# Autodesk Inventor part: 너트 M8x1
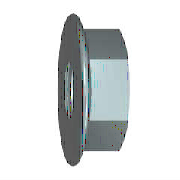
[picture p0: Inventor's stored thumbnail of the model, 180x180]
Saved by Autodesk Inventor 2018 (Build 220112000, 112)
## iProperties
Created: 2015-12
Part Number: 너트 M8x1
Material: 스테인리스강
Description: 플랜지붙이 6각 너트 - 일반 스레드
Document SubType Name: Modeling
Standard: ISO 4161
Designer: mdu
Standard Revision: 2판 1999-03-15
Standards Organization: ISO
Language: ko-KR
Size Designation: M8
Categories: <MemberInstance><Categories><Category DisplayName="조임쇠" InternalName="e4da775c-781d-43d5-af7c-5136215cf5a6" Mnemonic="FSTN"><Category DisplayName="너트" InternalN
Density: 8.08 g/cm^3
Mass: 8.84458 g
Surface Area: 8.9064 cm^2
Volume: 1.09463 cm^3
Appearance: 강철
Author: mdu
IsCustomPart: 1
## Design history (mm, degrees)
sketch "스케치1"
  geometry: L1 (-1.844, 0)-(9.641, 0) reference; L2 (3.107, 6.5)-(2.288, 8.257); L3 (3.107, 6.5)-(8, 6.5); L4 (8, 6.5)-(8, 0); L5 (3.107, 6.5)-(3.107, 0); L6 (0, -1.835)-(0, 11.01) reference; A1 r 1.2 centre (1.2, 7.75) between (2.288, 8.257) and (0, 7.75); 1 further point
  constraints: 8 end point, 3 point on line, 2 perpendicular, 2 point on circle, 2 tangent, 1 centre point, 1 parallel
  dimensions: "d2" = 13 diameter of L3 L1 (= SW); "d4" = 17.9 dimension on A1 L1 (= LADI); "d5" = 1.2 radius of A1 (= PHH); "d15" = 8 distance between parallel lines of L4 L6 (= KOH); "d16" = 25 deg angle of L6 L2 (= KEWI)
revolve "링" sketch "스케치1" stored, may be unused: angle "d8" = 90 deg
sketch "스케치2"
  geometry: L1 (-6.5, -3.753)-(-6.5, 3.753); L2 (-6.5, 3.753)-(0, 7.506); L3 (0, 7.506)-(6.5, 3.753); L4 (6.5, 3.753)-(6.5, -3.753); L5 (6.5, -3.753)-(0, -7.506); L6 (0, -7.506)-(-6.5, -3.753); C1 r 4.9 at (0, 0); C2 r 7.75 at (0, 0) reference; 1 further point
  constraints: 12 end point, 1 centre point, 1 coincident, 1 vertical, 11 other
  dimensions: "d6" = 15.01111 distance of L5.end L2.end (= 1.1547 x SW)
extrude "본체" join sketch "스케치2" distance "d7" = 8 (= KOH); taper "d9" = 0 deg
sketch "스케치3"
  geometry: L1 (2.638, 7.506)-(8, 7.506) reference; L2 (8, 3.753)-(8, 7.506) reference; L3 (0, -7.75)-(0, 7.75) reference; L4 (-1.6, 0)-(9.6, 0) reference; L5 (7.419, 7.506)-(8, 6.5)
  constraints: 2 end point, 2 point on line
  dimensions: "d10" = 30 deg angle of L2 L5 (= ANG1); "d11" = 13 diameter of L5.end L4 (= SW0)
revolve "모따기1" sketch "스케치3" stored, may be unused: angle "d24" = 90 deg
sketch "스케치4"
  geometry: C1 r 7.75 at (0, 0) reference; 1 further point
  constraints: 1 coincident
hole "스레드" sketch "스케치4" at (0, 0) diameter "d25" = 6.917; stored, may be unused: countersink angle "d29" = 82 deg, drill point angle "d31" = 118 deg; dims "d26" = 6, "d27" = 4, "d28" = 2, "d30" = 8
workaxis "Work Axis1"
workplane "Work Plane1"
body "Solid1"
chamfer "모따기2" distance "d12" = 0.67658 (= -0.5 x GD1 + 0.5 x NND); stored, may be unused: angle "d13" = 30 deg, second distance "d46" = 0.67658 (= -0.5 x GD1 + 0.5 x NND)
chamfer "모따기3" distance "d51" = 0.67658 (= -0.5 x GD1 + 0.5 x NND); stored, may be unused: second distance "d52" = 2, angle "d53" = 45 deg
other parameters: "ANG1" = 30 deg [user parameter; used in 1 equation term], "KEWI" = 25 deg [user parameter; used in 1 equation term], "NND" = 8 [user parameter; used in 4 equation terms], "LADI" = 17.9 [user parameter; used in 2 equation terms], "SW" = 13 [user parameter; used in 3 equation terms], "PHH" = 1.2 [user parameter; used in 3 equation terms], "KOH" = 8 (= NND) [user parameter; used in 2 equation terms], "SW0" = 13 [user parameter; used in 1 equation term], "GD1" = 6.64684 (computed from THREADDIA, PTC, TOA) [user parameter; used in 3 equation terms], "d1" = 17.9 (= LADI), "d3" = 1.2 (= PHH), "d45" = 0, "d47" = 0, "d49" = 0, "d54" = 0, "GUL" = 0.67658 (= 0.541266 x PTC) [user parameter], "TPU" = 8 (computed from PTC) [user parameter], "RR" = 1.2 (= PHH) [user parameter], "THREADDIA" = 8 [user parameter; used in 1 equation term], "TOA" = 30 deg [user parameter; used in 1 equation term], "PTC" = 1.25 [user parameter; used in 4 equation terms], "GAL" = 0.67658 (= 0.541266 x PTC) [user parameter], "E0" = 15.015 (= 1.155 x SW) [user parameter]
